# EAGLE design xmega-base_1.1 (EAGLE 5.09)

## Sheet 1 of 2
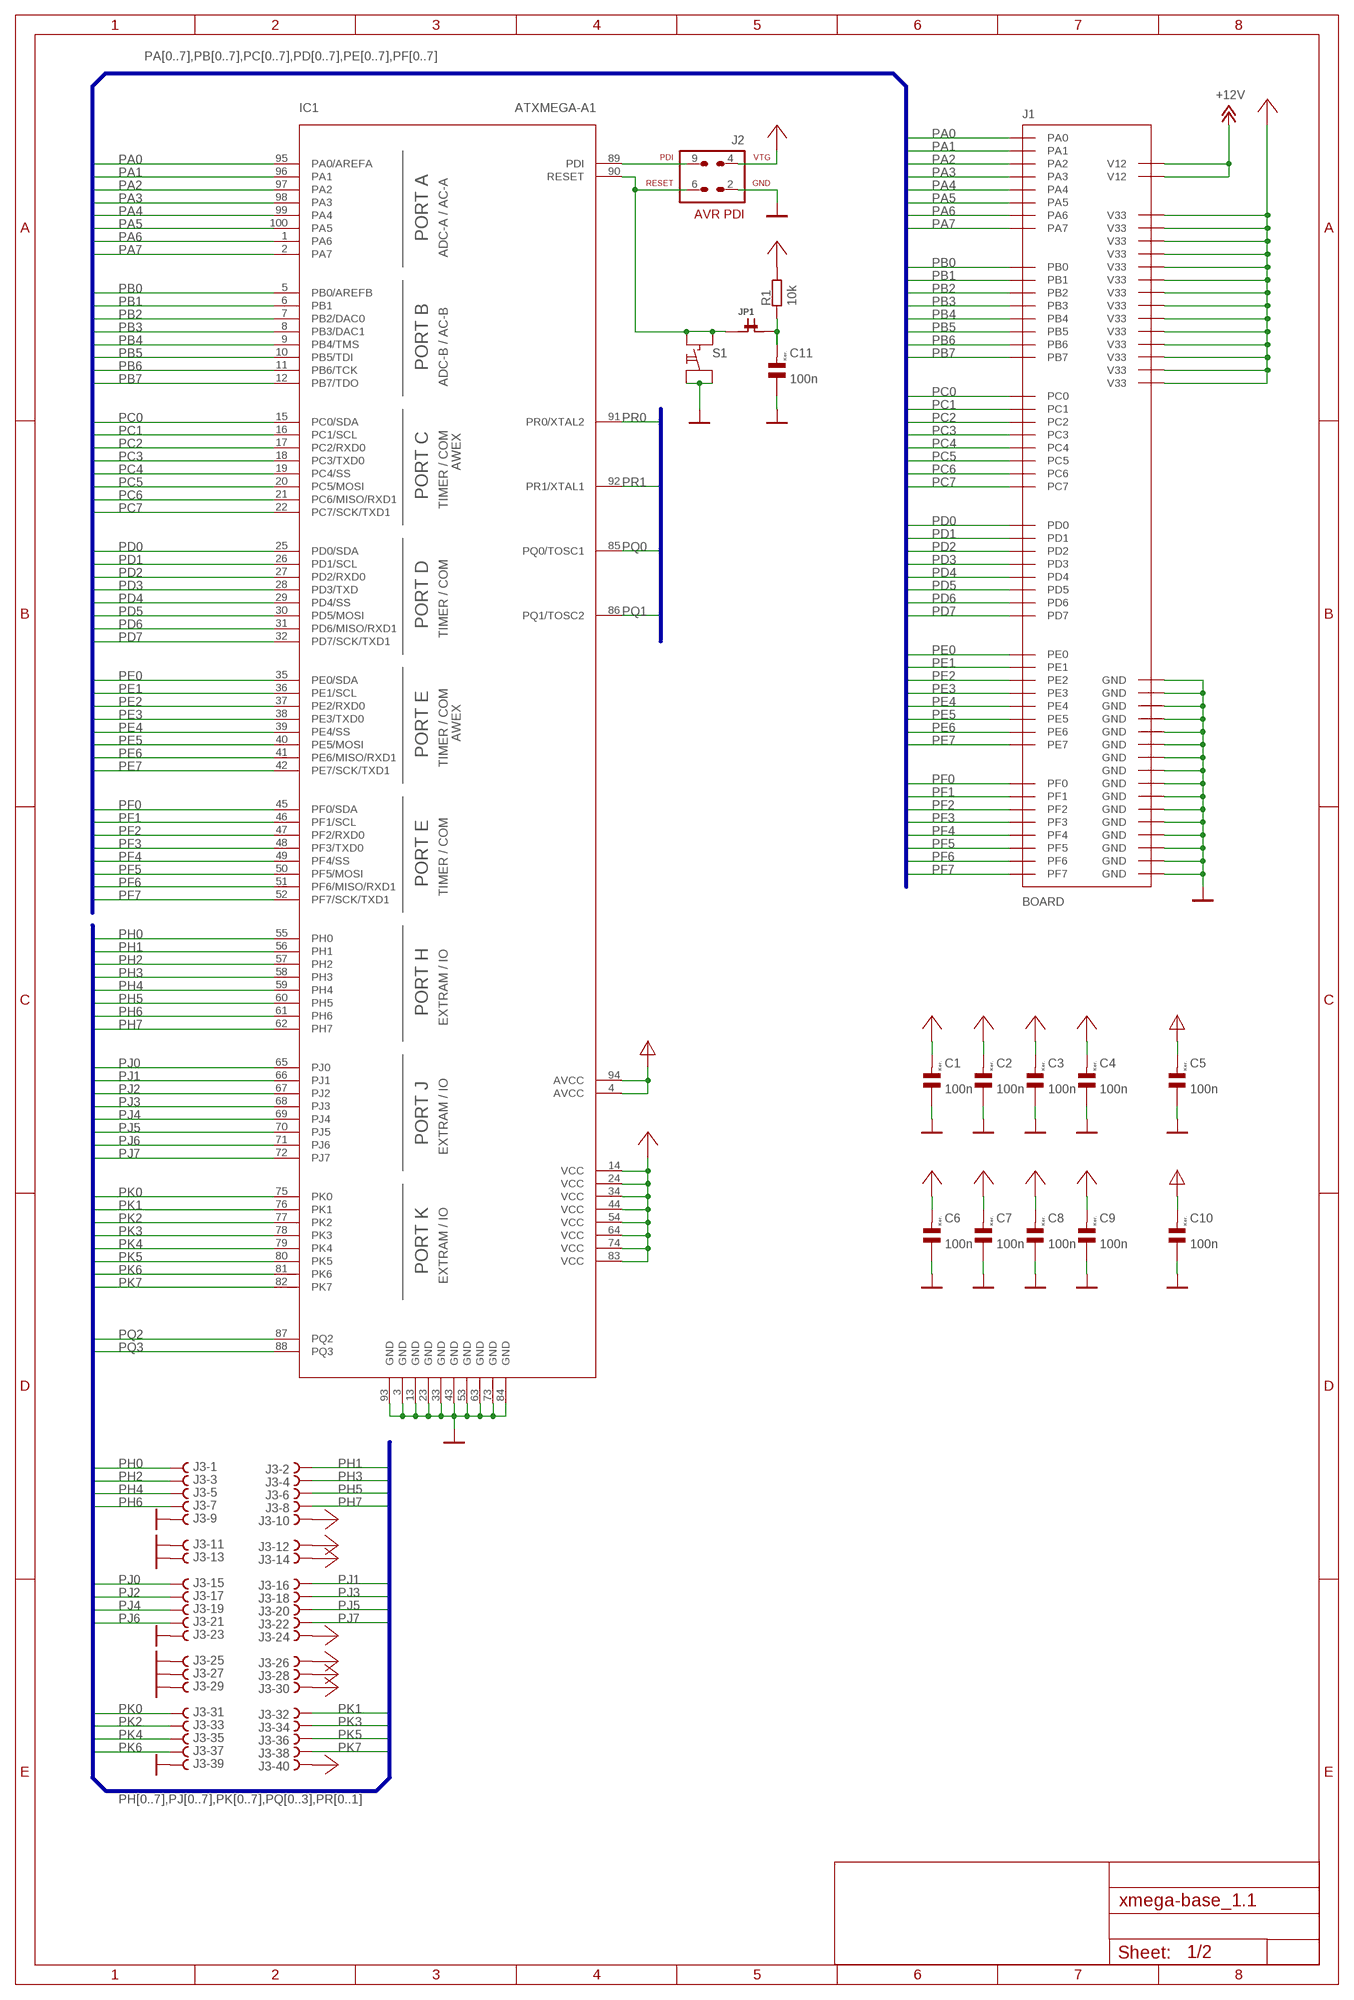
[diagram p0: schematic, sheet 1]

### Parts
C1  100n  C_KER_0805  [C0805K]
C2  100n  C_KER_0805  [C0805K]
C3  100n  C_KER_0805  [C0805K]
C4  100n  C_KER_0805  [C0805K]
C5  100n  C_KER_0805  [C0805K]
C6  100n  C_KER_0805  [C0805K]
C7  100n  C_KER_0805  [C0805K]
C8  100n  C_KER_0805  [C0805K]
C9  100n  C_KER_0805  [C0805K]
C10  100n  C_KER_0805  [C0805K]
C11  100n  C_KER_0805  [C0805K]
IC1  ATXMEGA-A1  [TQFP100]
J1  BOARD  [BOARD]
J2  AVR-PDIHW10  [ML10L]
J3  SL40S_2X20G_254  [SL2X20G_254]
JP1  JP1  [JP1]
R1  10k  R_0805  [R0805]
S1  PHAP3301  [PHAP3301]

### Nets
+12V: J1.P$1(V12) J1.P$2(V12) ; also sheet 2
AVCC: C5.2 C10.2 IC1.4(AVCC) IC1.94(AVCC) ; also sheet 2
GND: C1.1 C2.1 C3.1 C4.1 C5.1 C6.1 C7.1 C8.1 C9.1 C10.1 C11.1 IC1.3(GND) IC1.13(GND) IC1.23(GND) IC1.33(GND) IC1.43(GND) IC1.53(GND) IC1.63(GND) IC1.73(GND) IC1.84(GND) IC1.93(GND) J1.P$3(GND) J1.P$4(GND) J1.P$15(GND) J1.P$16(GND) J1.P$27(GND) J1.P$28(GND) J1.P$39(GND) J1.P$40(GND) J1.P$43(GND) J1.P$44(GND) J1.P$55(GND) J1.P$56(GND) J1.P$67(GND) J1.P$68(GND) J1.P$79(GND) J1.P$80(GND) J2.2(GND) J3.9 J3.11 J3.13 J3.23 J3.25 J3.27 J3.29 J3.39 S1.3 S1.4 ; also sheet 2
N$1: IC1.89(PDI) J2.9(PDI)
N$3: C11.2 JP1.2 R1.1
PA0: IC1.95(PA0/AREFA) J1.P$5(PA0)
PA1: IC1.96(PA1) J1.P$6(PA1)
PA2: IC1.97(PA2) J1.P$7(PA2)
PA3: IC1.98(PA3) J1.P$8(PA3)
PA4: IC1.99(PA4) J1.P$9(PA4)
PA5: IC1.100(PA5) J1.P$10(PA5)
PA6: IC1.1(PA6) J1.P$11(PA6)
PA7: IC1.2(PA7) J1.P$12(PA7)
PB0: IC1.5(PB0/AREFB) J1.P$17(PB0)
PB1: IC1.6(PB1) J1.P$18(PB1)
PB2: IC1.7(PB2/DAC0) J1.P$19(PB2)
PB3: IC1.8(PB3/DAC1) J1.P$20(PB3)
PB4: IC1.9(PB4/TMS) J1.P$21(PB4)
PB5: IC1.10(PB5/TDI) J1.P$22(PB5)
PB6: IC1.11(PB6/TCK) J1.P$23(PB6)
PB7: IC1.12(PB7/TDO) J1.P$24(PB7)
PC0: IC1.15(PC0/SDA) J1.P$29(PC0)
PC1: IC1.16(PC1/SCL) J1.P$30(PC1)
PC2: IC1.17(PC2/RXD0) J1.P$31(PC2)
PC3: IC1.18(PC3/TXD0) J1.P$32(PC3)
PC4: IC1.19(PC4/SS) J1.P$33(PC4)
PC5: IC1.20(PC5/MOSI) J1.P$34(PC5)
PC6: IC1.21(PC6/MISO/RXD1) J1.P$35(PC6)
PC7: IC1.22(PC7/SCK/TXD1) J1.P$36(PC7)
PD0: IC1.25(PD0/SDA) J1.P$76(PD0)
PD1: IC1.26(PD1/SCL) J1.P$75(PD1)
PD2: IC1.27(PD2/RXD0) J1.P$74(PD2) ; also sheet 2
PD3: IC1.28(PD3/TXD) J1.P$73(PD3) ; also sheet 2
PD4: IC1.29(PD4/SS) J1.P$72(PD4) ; also sheet 2
PD5: IC1.30(PD5/MOSI) J1.P$71(PD5) ; also sheet 2
PD6: IC1.31(PD6/MISO/RXD1) J1.P$70(PD6) ; also sheet 2
PD7: IC1.32(PD7/SCK/TXD1) J1.P$69(PD7) ; also sheet 2
PE0: IC1.35(PE0/SDA) J1.P$64(PE0)
PE1: IC1.36(PE1/SCL) J1.P$63(PE1)
PE2: IC1.37(PE2/RXD0) J1.P$62(PE2)
PE3: IC1.38(PE3/TXD0) J1.P$61(PE3)
PE4: IC1.39(PE4/SS) J1.P$60(PE4)
PE5: IC1.40(PE5/MOSI) J1.P$59(PE5)
PE6: IC1.41(PE6/MISO/RXD1) J1.P$58(PE6)
PE7: IC1.42(PE7/SCK/TXD1) J1.P$57(PE7)
PF0: IC1.45(PF0/SDA) J1.P$52(PF0)
PF1: IC1.46(PF1/SCL) J1.P$51(PF1)
PF2: IC1.47(PF2/RXD0) J1.P$50(PF2)
PF3: IC1.48(PF3/TXD0) J1.P$49(PF3)
PF4: IC1.49(PF4/SS) J1.P$48(PF4)
PF5: IC1.50(PF5/MOSI) J1.P$47(PF5)
PF6: IC1.51(PF6/MISO/RXD1) J1.P$46(PF6)
PF7: IC1.52(PF7/SCK/TXD1) J1.P$45(PF7)
PH0: IC1.55(PH0) J3.1
PH1: IC1.56(PH1) J3.2
PH2: IC1.57(PH2) J3.3
PH3: IC1.58(PH3) J3.4
PH4: IC1.59(PH4) J3.5
PH5: IC1.60(PH5) J3.6
PH6: IC1.61(PH6) J3.7
PH7: IC1.62(PH7) J3.8
PJ0: IC1.65(PJ0) J3.15
PJ1: IC1.66(PJ1) J3.16
PJ2: IC1.67(PJ2) J3.17
PJ3: IC1.68(PJ3) J3.18
PJ4: IC1.69(PJ4) J3.19
PJ5: IC1.70(PJ5) J3.20
PJ6: IC1.71(PJ6) J3.21
PJ7: IC1.72(PJ7) J3.22
PK0: IC1.75(PK0) J3.31
PK1: IC1.76(PK1) J3.32
PK2: IC1.77(PK2) J3.33
PK3: IC1.78(PK3) J3.34
PK4: IC1.79(PK4) J3.35
PK5: IC1.80(PK5) J3.36
PK6: IC1.81(PK6) J3.37
PK7: IC1.82(PK7) J3.38
PQ0: IC1.85(PQ0/TOSC1) ; also sheet 2
PQ1: IC1.86(PQ1/TOSC2) ; also sheet 2
PQ2: IC1.87(PQ2) ; also sheet 2
PQ3: IC1.88(PQ3) ; also sheet 2
PR0: IC1.91(PR0/XTAL2) ; also sheet 2
PR1: IC1.92(PR1/XTAL1) ; also sheet 2
RESET: IC1.90(RESET) J2.6(RESET) JP1.1 S1.1 S1.2
VCC: C1.2 C2.2 C3.2 C4.2 C6.2 C7.2 C8.2 C9.2 IC1.14(VCC) IC1.24(VCC) IC1.34(VCC) IC1.44(VCC) IC1.54(VCC) IC1.64(VCC) IC1.74(VCC) IC1.83(VCC) J1.P$13(V33) J1.P$14(V33) J1.P$25(V33) J1.P$26(V33) J1.P$37(V33) J1.P$38(V33) J1.P$41(V33) J1.P$42(V33) J1.P$53(V33) J1.P$54(V33) J1.P$65(V33) J1.P$66(V33) J1.P$77(V33) J1.P$78(V33) J2.4(VTG) J3.10 J3.12 J3.14 J3.24 J3.26 J3.28 J3.30 J3.40 R1.2 ; also sheet 2

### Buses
PA[0..7],PB[0..7],PC[0..7],PD[0..7],PE[0..7],PF[0..7]
PH[0..7],PJ[0..7],PK[0..7],PQ[0..3],PR[0..1]

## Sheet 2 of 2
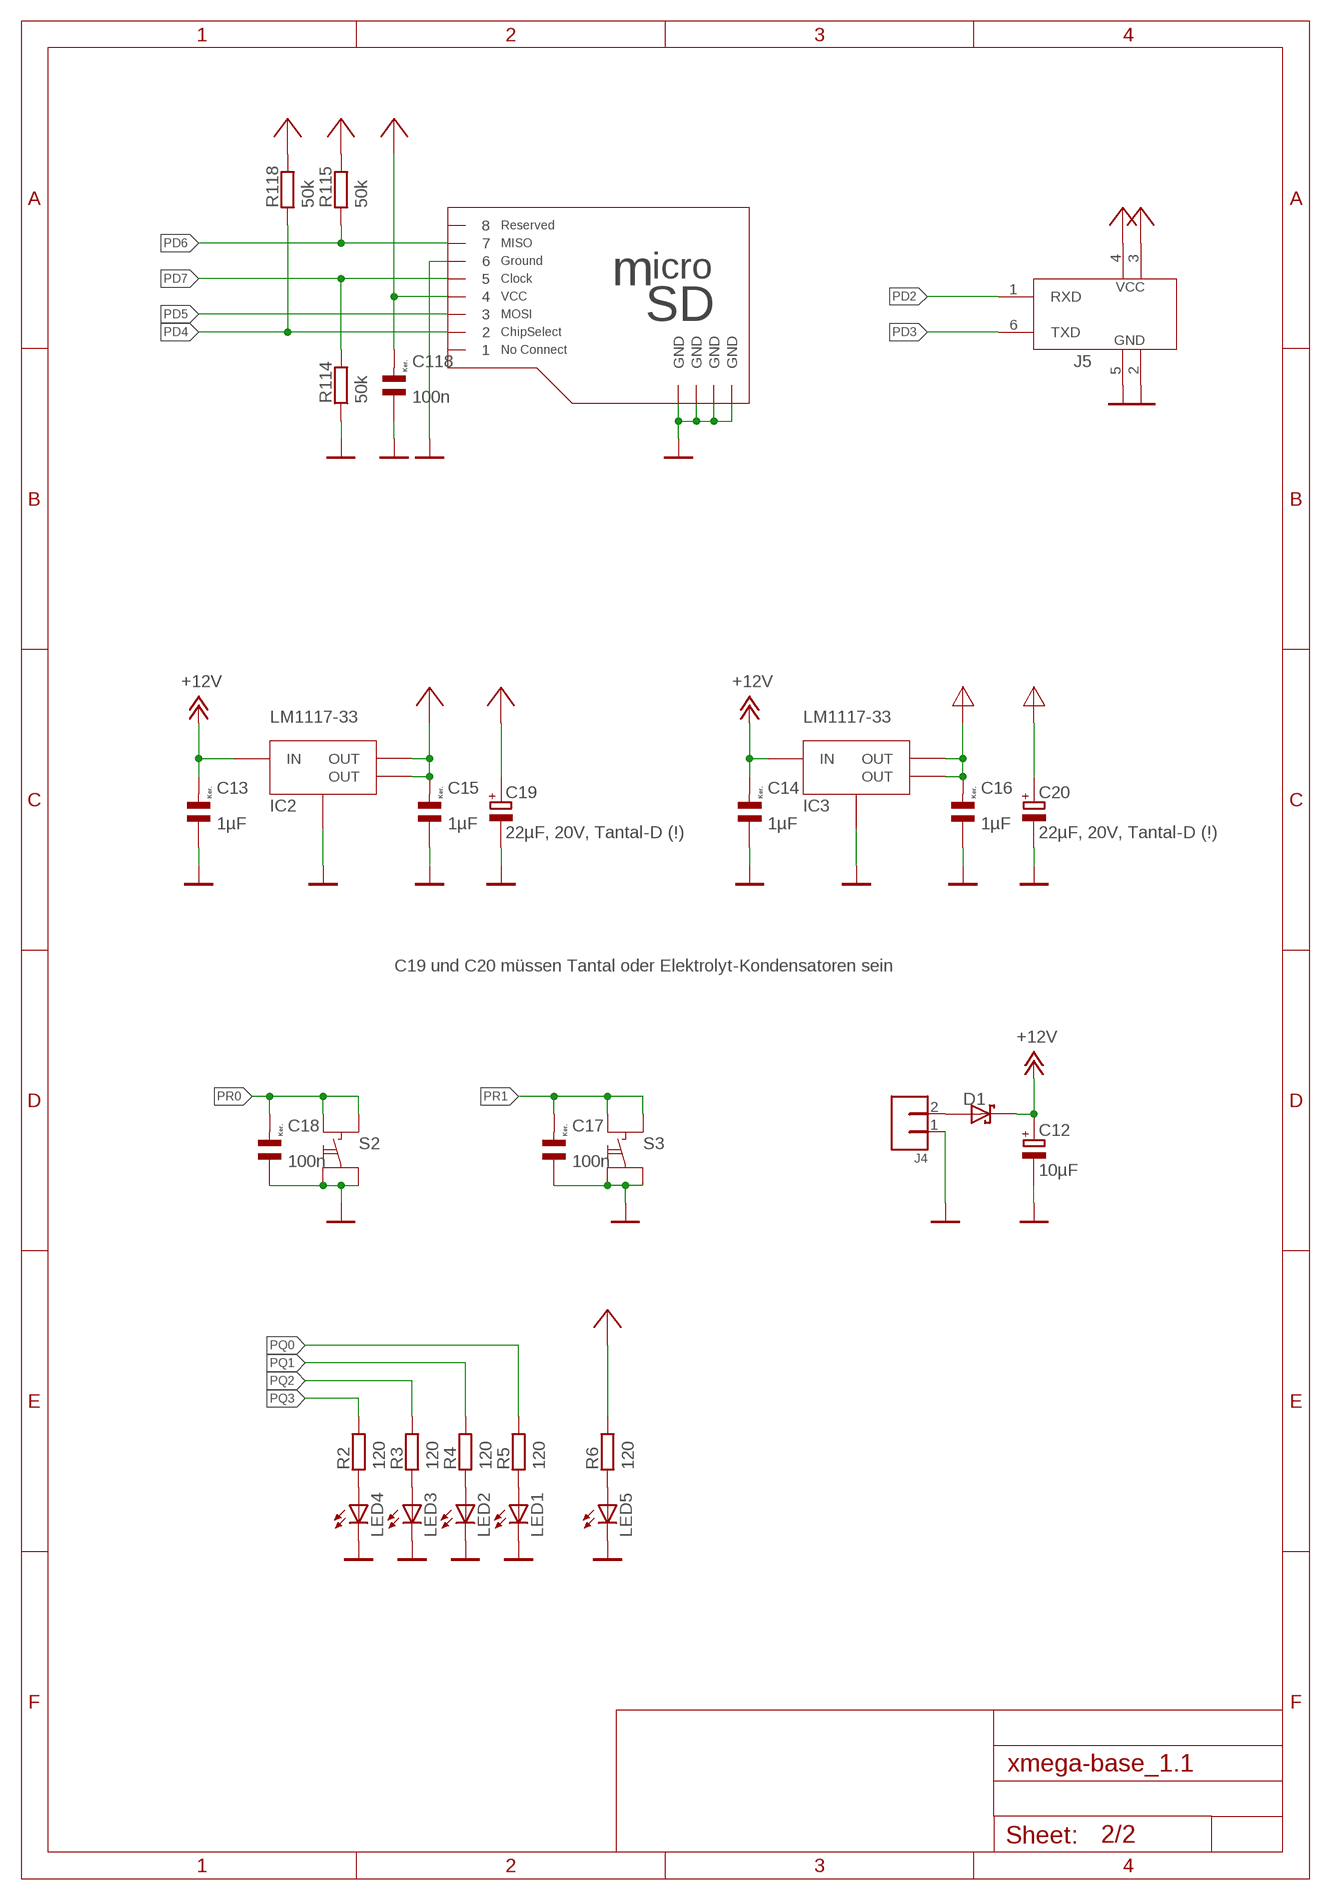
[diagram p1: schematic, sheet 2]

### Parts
C12  10µF  ELKO_SMD_05  [153CLV-0505]
C13  1µF  C_KER_1206  [C1206K]
C14  1µF  C_KER_1206  [C1206K]
C15  1µF  C_KER_1206  [C1206K]
C16  1µF  C_KER_1206  [C1206K]
C17  100n  C_KER_0805  [C0805K]
C18  100n  C_KER_0805  [C0805K]
C19  22µF, 20V, Tantal-D (!)  ELKO_SMD_D  [SMC_D]
C20  22µF, 20V, Tantal-D (!)  ELKO_SMD_D  [SMC_D]
C118  100n  C_KER_0805  [C0805K]
D1  SCHOTTKY-DIODE-SMB  [SMB]
IC2  LM1117-33  [SOT223]
IC3  LM1117-33  [SOT223]
J4  SL2_AKL_182  [AKL182-02]
J5  RS232_6PINHW  [ML6L]
J104  MICRO_SD_ST1  [JAE_ST1_MICOSD]
LED1  LEDCHIP-LED1206  [CHIPLED_1206]
LED2  LEDCHIP-LED1206  [CHIPLED_1206]
LED3  LEDCHIP-LED1206  [CHIPLED_1206]
LED4  LEDCHIP-LED1206  [CHIPLED_1206]
LED5  LEDCHIP-LED1206  [CHIPLED_1206]
R2  120  R_0805  [R0805]
R3  120  R_0805  [R0805]
R4  120  R_0805  [R0805]
R5  120  R_0805  [R0805]
R6  120  R_0805  [R0805]
R114  50k  R_0805  [R0805]
R115  50k  R_0805  [R0805]
R118  50k  R_0805  [R0805]
S2  PHAP3301  [PHAP3301]
S3  PHAP3301  [PHAP3301]

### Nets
+12V: C12.+ C13.2 C14.2 D1.C IC2.3(IN) IC3.3(IN) ; also sheet 1
AVCC: C16.2 C20.+ IC3.2(OUT) IC3.4(OUT) ; also sheet 1
GND: C12.- C13.1 C14.1 C15.1 C16.1 C17.1 C18.1 C19.- C20.- C118.1 IC2.1(GND) IC3.1(GND) J4.1 J5.2(GND) J5.5(GND) J104.6 J104.GND1(GND) J104.GND2(GND) J104.GND3(GND) J104.GND4(GND) LED1.C LED2.C LED3.C LED4.C LED5.C R114.1 S2.3 S2.4 S3.3 S3.4 ; also sheet 1
N$2: D1.A J4.2
N$4: LED4.A R2.1
N$5: LED3.A R3.1
N$6: LED2.A R4.1
N$7: LED1.A R5.1
N$8: LED5.A R6.1
PD2: J5.1(RXD) ; also sheet 1
PD3: J5.6(TXD) ; also sheet 1
PD4: J104.2 R118.1 ; also sheet 1
PD5: J104.3 ; also sheet 1
PD6: J104.7 R115.1 ; also sheet 1
PD7: J104.5 R114.2 ; also sheet 1
PQ0: R5.2 ; also sheet 1
PQ1: R4.2 ; also sheet 1
PQ2: R3.2 ; also sheet 1
PQ3: R2.2 ; also sheet 1
PR0: C18.2 S2.1 S2.2 ; also sheet 1
PR1: C17.2 S3.1 S3.2 ; also sheet 1
VCC: C15.2 C19.+ C118.2 IC2.2(OUT) IC2.4(OUT) J5.3(VCC) J5.4(VCC) J104.4 R6.2 R115.2 R118.2 ; also sheet 1
Unconnected: J104.1 J104.8

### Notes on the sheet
- C19 und C20 müssen Tantal oder Elektrolyt-Kondensatoren sein

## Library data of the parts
C1-C11 C13-C18 C118 = lib-rcl:C_KER
C12 C19 C20 = lib-rcl:ELKO
D1 = lib-halbleiter:SCHOTTKY-DIODE
IC1 = lib-avr:ATXMEGA-A1
IC2 IC3 = lib-ic:LM1117-*: Alternativ auch TLV1117 von TI
J1 = xmega-board:BOARD
J2 = lib-avr:AVR-PDI
J3 = lib-connectors:SL40S?
J4 = lib-connectors:SL2?
J5 = lib-com:RS232_6PIN
J104 = lib-misc:MICRO_SD
JP1 = lib-connectors:JP1
LED1-LED5 = lib-halbleiter:LED
R1-R6 R114 R115 R118 = lib-rcl:R: RESISTOR, European symbol
S1-S3 = lib-switch:PHAP?*

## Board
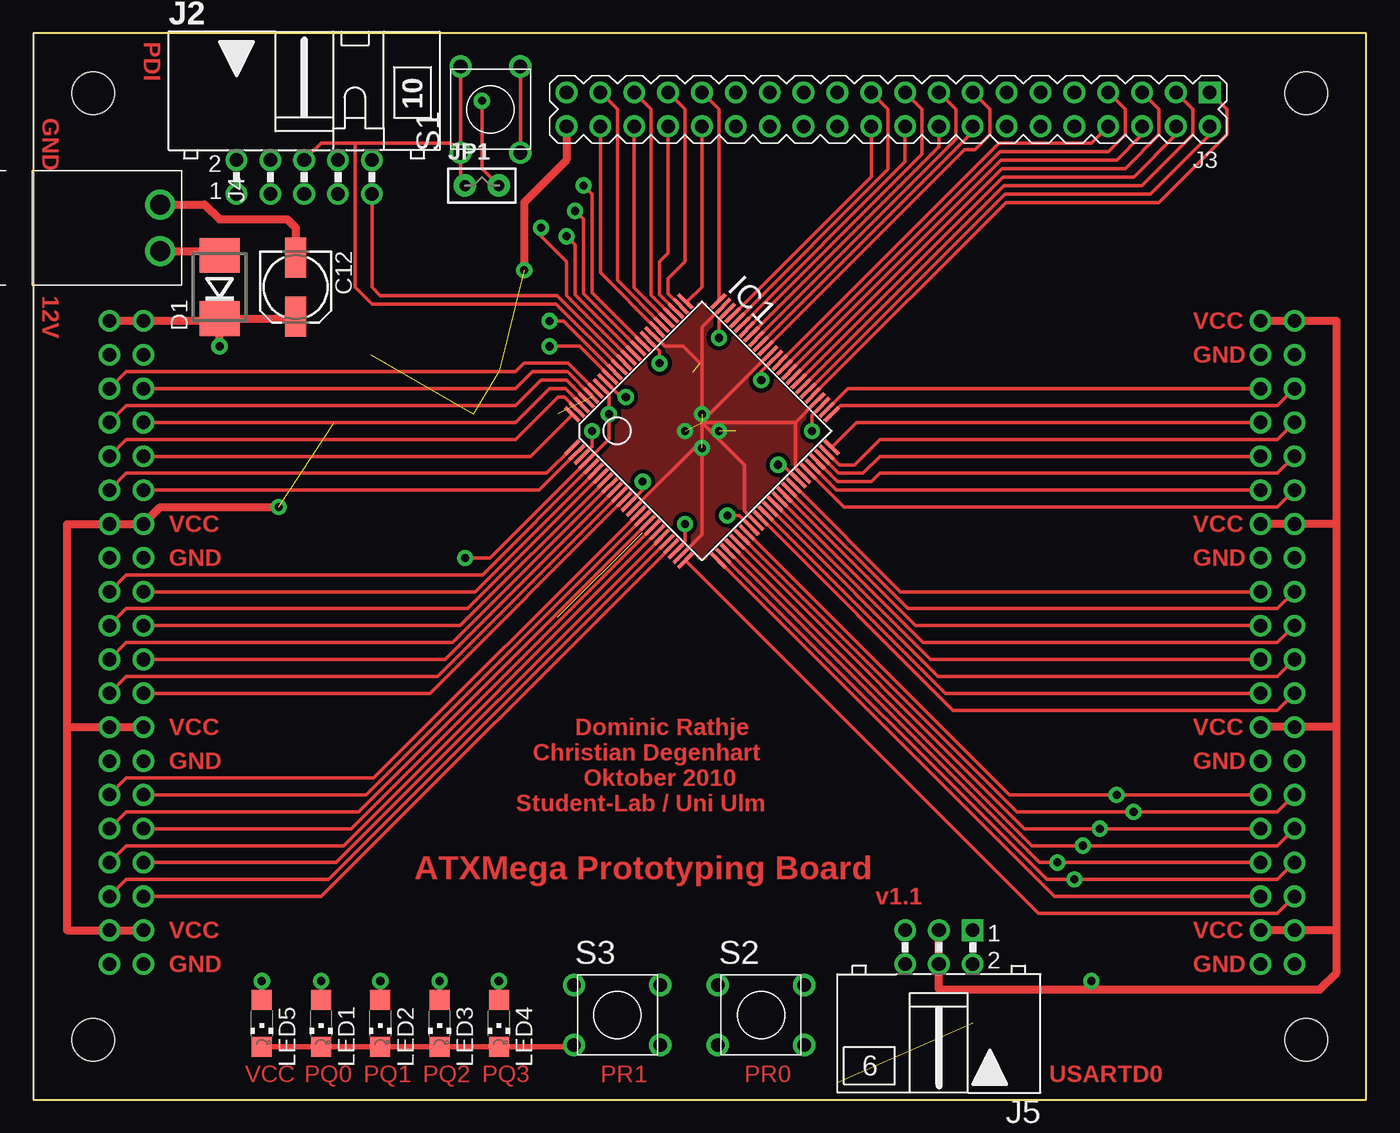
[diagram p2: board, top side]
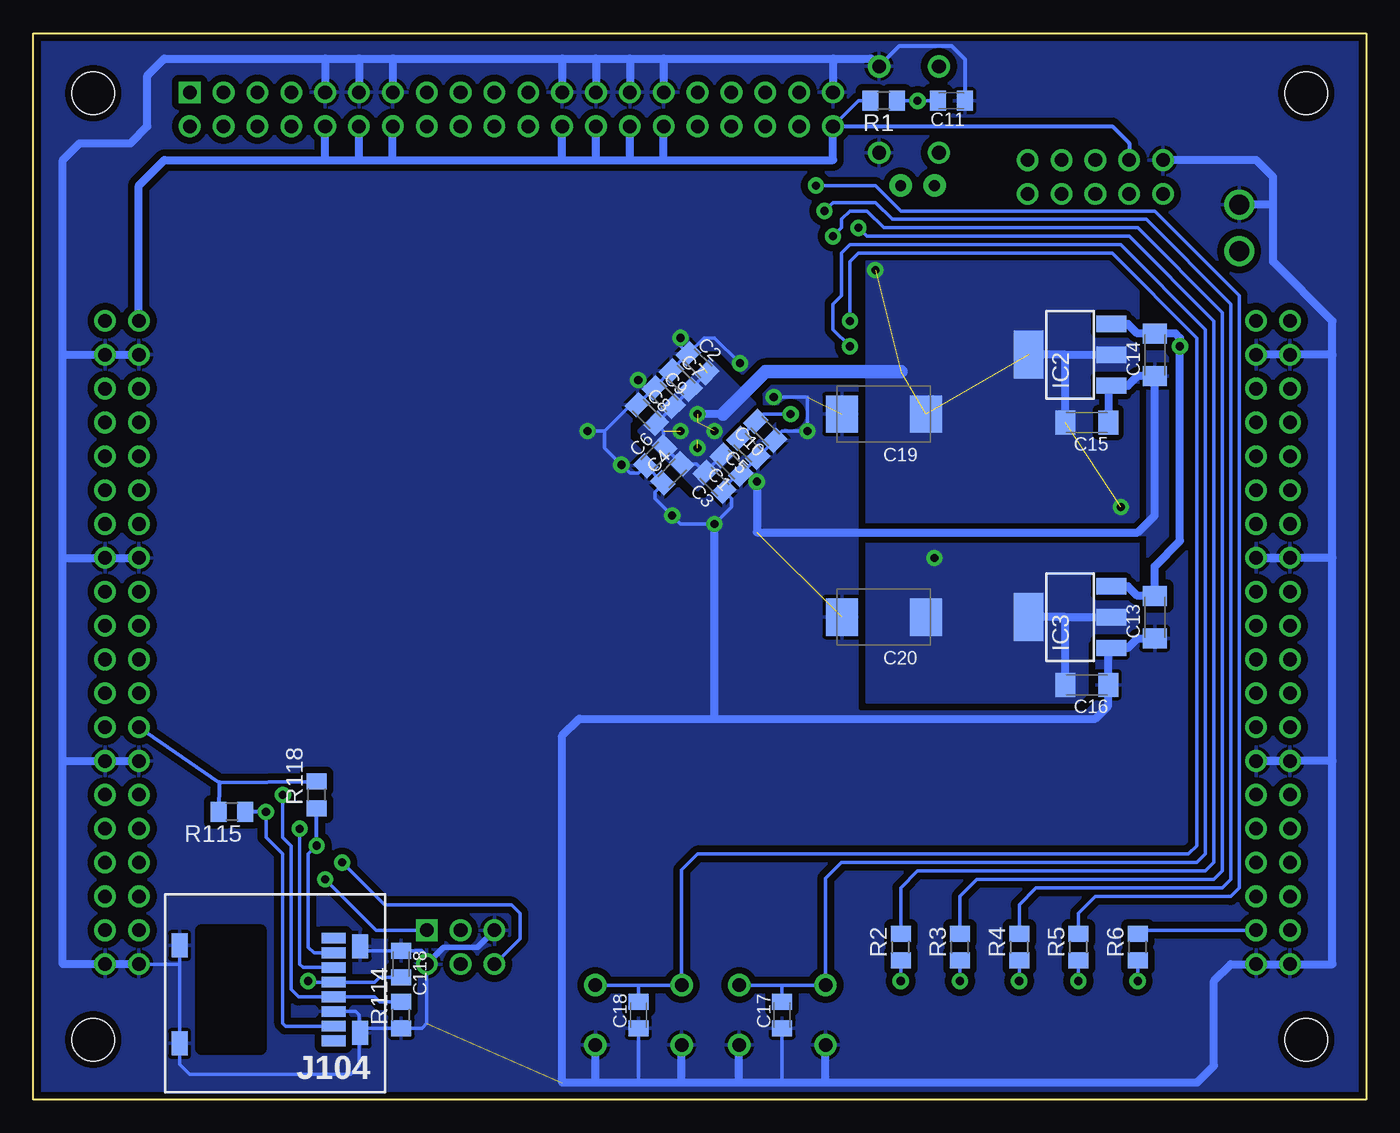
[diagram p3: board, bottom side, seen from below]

Size 100 x 80 mm. Coordinates in mm from the lower left corner, seen from the top.
Copper layers (1*16): Top 0.0254mm / dielectric 1.4986mm / Bottom 0.0254mm
Design rules "uni_ulm": minimum track width 8mil, minimum drill 16mil, track to track 8mil, track to pad 8mil, pad to pad 8mil, via to via 8mil, smd to smd 8mil, copper to edge 20mil, drill to drill 8mil, minimum pad ring 12mil, minimum via ring 12mil, stop-mask expansion 4mil, vias tented up to drill 24mil, thermal gap 10mil

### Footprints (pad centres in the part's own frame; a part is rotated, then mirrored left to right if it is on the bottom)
C0805K = smd 1.2 x 1.5: 1 -1,0; 2 1,0
153CLV-0505 = smd 3 x 1.6: + 2.2,0; - -2.2,0
C1206K = smd 1.5 x 1.8: 1 -1.6,0; 2 1.6,0
SMC_D = smd 2.4 x 2.8: + -3.15,0; - 3.15,0
SMB = smd 2.6 x 3: A 2.368,0; C -2.368,0
TQFP100 = smd 0.27 x 1.5: 1 -6,-7.75; 2 -5.5,-7.75; 3 -5,-7.75; 4 -4.5,-7.75; 5 -4,-7.75; 6 -3.5,-7.75; 7 -3,-7.75; 8 -2.5,-7.75; 9 -2,-7.75; 10 -1.5,-7.75; 11 -1,-7.75; 12 -0.5,-7.75; 13 0,-7.75; 14 0.5,-7.75; 15 1,-7.75; 16 1.5,-7.75; 17 2,-7.75; 18 2.5,-7.75; 19 3,-7.75; 20 3.5,-7.75; 21 4,-7.75; 22 4.5,-7.75; 23 5,-7.75; 24 5.5,-7.75; 25 6,-7.75; 51 6,7.75; 52 5.5,7.75; 53 5,7.75; 54 4.5,7.75; 55 4,7.75; 56 3.5,7.75; 57 3,7.75; 58 2.5,7.75; 59 2,7.75; 60 1.5,7.75; 61 1,7.75; 62 0.5,7.75; 63 0,7.75; 64 -0.5,7.75; 65 -1,7.75; 66 -1.5,7.75; 67 -2,7.75; 68 -2.5,7.75; 69 -3,7.75; 70 -3.5,7.75; 71 -4,7.75; 72 -4.5,7.75; 73 -5,7.75; 74 -5.5,7.75; 75 -6,7.75 | smd 1.5 x 0.27: 26 7.75,-6; 27 7.75,-5.5; 28 7.75,-5; 29 7.75,-4.5; 30 7.75,-4; 31 7.75,-3.5; 32 7.75,-3; 33 7.75,-2.5; 34 7.75,-2; 35 7.75,-1.5; 36 7.75,-1; 37 7.75,-0.5; 38 7.75,0; 39 7.75,0.5; 40 7.75,1; 41 7.75,1.5; 42 7.75,2; 43 7.75,2.5; 44 7.75,3; 45 7.75,3.5; 46 7.75,4; 47 7.75,4.5; 48 7.75,5; 49 7.75,5.5; 50 7.75,6; 76 -7.75,6; 77 -7.75,5.5; 78 -7.75,5; 79 -7.75,4.5; 80 -7.75,4; 81 -7.75,3.5; 82 -7.75,3; 83 -7.75,2.5; 84 -7.75,2; 85 -7.75,1.5; 86 -7.75,1; 87 -7.75,0.5; 88 -7.75,0; 89 -7.75,-0.5; 90 -7.75,-1; 91 -7.75,-1.5; 92 -7.75,-2; 93 -7.75,-2.5; 94 -7.75,-3; 95 -7.75,-3.5; 96 -7.75,-4; 97 -7.75,-4.5; 98 -7.75,-5; 99 -7.75,-5.5; 100 -7.75,-6
SOT223 = smd 1.219 x 2.235: 1 -2.311,-3.099; 2 0,-3.099; 3 2.311,-3.099 | smd 3.6 x 2.2: 4 0,3.099
BOARD = drill 1.016 pad 1.626 round: P$1 5.715,58.42; P$2 8.255,58.42; P$3 5.715,55.88; P$4 8.255,55.88; P$5 5.715,53.34; P$6 8.255,53.34; P$7 5.715,50.8; P$8 8.255,50.8; P$9 5.715,48.26; P$10 8.255,48.26; P$11 5.715,45.72; P$12 8.255,45.72; P$13 5.715,43.18; P$14 8.255,43.18; P$15 5.715,40.64; P$16 8.255,40.64; P$17 5.715,38.1; P$18 8.255,38.1; P$19 5.715,35.56; P$20 8.255,35.56; P$21 5.715,33.02; P$22 8.255,33.02; P$23 5.715,30.48; P$24 8.255,30.48; P$25 5.715,27.94; P$26 8.255,27.94; P$27 5.715,25.4; P$28 8.255,25.4; P$29 5.715,22.86; P$30 8.255,22.86; P$31 5.715,20.32; P$32 8.255,20.32; P$33 5.715,17.78; P$34 8.255,17.78; P$35 5.715,15.24; P$36 8.255,15.24; P$37 5.715,12.7; P$38 8.255,12.7; P$39 5.715,10.16; P$40 8.255,10.16; P$41 92.075,58.42; P$42 94.615,58.42; P$43 92.075,55.88; P$44 94.615,55.88; P$45 92.075,53.34; P$46 94.615,53.34; P$47 92.075,50.8; P$48 94.615,50.8; P$49 92.075,48.26; P$50 94.615,48.26; P$51 92.075,45.72; P$52 94.615,45.72; P$53 92.075,43.18; P$54 94.615,43.18; P$55 92.075,40.64; P$56 94.615,40.64; P$57 92.075,38.1; P$58 94.615,38.1; P$59 92.075,35.56; P$60 94.615,35.56; P$61 92.075,33.02; P$62 94.615,33.02; P$63 92.075,30.48; P$64 94.615,30.48; P$65 92.075,27.94; P$66 94.615,27.94; P$67 92.075,25.4; P$68 94.615,25.4; P$69 92.075,22.86; P$70 94.615,22.86; P$71 92.075,20.32; P$72 94.615,20.32; P$73 92.075,17.78; P$74 94.615,17.78; P$75 92.075,15.24; P$76 94.615,15.24; P$77 92.075,12.7; P$78 94.615,12.7; P$79 92.075,10.16; P$80 94.615,10.16 | hole 3.2: 4.5,4.5; 95.5,4.5; 95.5,75.5; 4.5,75.5
ML10L = drill 1.016 pad 1.626 round: 1 -5.08,-1.27; 2 -5.08,1.27; 3 -2.54,-1.27; 4 -2.54,1.27; 5 0,-1.27; 6 0,1.27; 7 2.54,-1.27; 8 2.54,1.27; 9 5.08,-1.27; 10 5.08,1.27
SL2X20G_254 = drill 1.016 pad 1.626 square: 1 -24.13,-1.27 | drill 1.016 pad 1.626 round: 2 -24.13,1.27; 3 -21.59,-1.27; 4 -21.59,1.27; 5 -19.05,-1.27; 6 -19.05,1.27; 7 -16.51,-1.27; 8 -16.51,1.27; 9 -13.97,-1.27; 10 -13.97,1.27; 11 -11.43,-1.27; 12 -11.43,1.27; 13 -8.89,-1.27; 14 -8.89,1.27; 15 -6.35,-1.27; 16 -6.35,1.27; 17 -3.81,-1.27; 18 -3.81,1.27; 19 -1.27,-1.27; 20 -1.27,1.27; 21 1.27,-1.27; 22 1.27,1.27; 23 3.81,-1.27; 24 3.81,1.27; 25 6.35,-1.27; 26 6.35,1.27; 27 8.89,-1.27; 28 8.89,1.27; 29 11.43,-1.27; 30 11.43,1.27; 31 13.97,-1.27; 32 13.97,1.27; 33 16.51,-1.27; 34 16.51,1.27; 35 19.05,-1.27; 36 19.05,1.27; 37 21.59,-1.27; 38 21.59,1.27; 39 24.13,-1.27; 40 24.13,1.27
AKL182-02 = drill 1.5 pad 2.184 round: 1 -1.75,0; 2 1.75,0
ML6L = drill 1.016 pad 1.626 square: 1 -2.54,-1.27 | drill 1.016 pad 1.626 round: 2 -2.54,1.27; 3 0,-1.27; 4 0,1.27; 5 2.54,-1.27; 6 2.54,1.27
JAE_ST1_MICOSD = smd 1.8 x 0.8: 1 0,-3.85; 2 0,-2.75; 3 0,-1.65; 4 0,-0.55; 5 0,0.55; 6 0,1.65; 7 0,2.75; 8 0,3.85 | smd 1.2 x 1.8: GND1 11.55,-3.3; GND2 11.55,4.05; GND3 -2,-3.25; GND4 -2,3.25
JP1 = drill 0.813 pad 1.676 round: 1 -1.27,0; 2 1.27,0
CHIPLED_1206 = smd 1.5 x 1.5: A 0,-1.75; C 0,1.75
R0805 = smd 1.2 x 1.5: 1 -1,0; 2 1,0
PHAP3301 = drill 1.016 pad 1.676 round: 1 -2.235,-3.251; 2 -2.235,3.226; 3 2.261,-3.251; 4 2.261,3.226

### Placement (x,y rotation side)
C1  47.62,47.62 135 bottom
C2  50.16,55.24 315 bottom
C3  48.9,46.35 135 bottom
C4  52.07,46.99 45 bottom
C5  46.35,48.9 135 bottom
C6  53.34,48.26 45 bottom
C7  51.44,53.98 315 bottom
C8  53.98,51.44 315 bottom
C9  52.7,52.7 315 bottom
C10  45.09,50.16 135 bottom
C11  31.11,74.93 180 bottom
C12  19.68,60.96 270 top
C13  15.88,36.2 90 bottom
C14  15.88,55.88 90 bottom
C15  20.95,50.8 180 bottom
C16  20.95,31.11 180 bottom
C17  43.81,6.35 90 bottom
C18  54.61,6.35 90 bottom
C19  36.2,51.44 180 bottom
C20  36.2,36.2 180 bottom
C118  72.39,10.16 270 bottom
D1  13.97,60.96 90 top
IC1  50.16,50.16 315 top
IC2  22.23,55.88 90 bottom
IC3  22.23,36.2 90 bottom
J1  0,0 0 top
J2  20.32,69.22 0 top
J3  64.14,74.3 180 top
J4  9.53,65.41 270 top
J5  67.94,11.43 180 top
J104  77.47,8.26 180 bottom
JP1  33.66,68.58 0 top
LED1  21.59,5.71 180 top
LED2  26.04,5.71 180 top
LED3  30.48,5.71 180 top
LED4  34.92,5.71 180 top
LED5  17.14,5.71 180 top
R1  36.2,74.93 180 bottom
R2  34.92,11.43 90 bottom
R3  30.48,11.43 90 bottom
R4  26.04,11.43 90 bottom
R5  21.59,11.43 90 bottom
R6  17.14,11.43 90 bottom
R114  72.39,6.35 90 bottom
R115  85.09,21.59 180 bottom
R118  78.74,22.86 90 bottom
S1  34.29,74.3 0 top
S2  54.61,6.35 270 top
S3  43.81,6.35 270 top

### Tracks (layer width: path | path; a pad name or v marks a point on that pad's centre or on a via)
+12V  (via drill 0.61 pad 0.81)
  Top 0.305: 13.97,58.42 D1.C
  Top 0.61: J1.P$1 J1.P$2 13.97,58.42 v13.97,56.52 | C12.+ 19.52,58.59 D1.C
  Bottom 0.61: IC3.3 17.87,38.51 17.16,37.8 C13.2 15.88,40.01 13.97,41.91 v13.97,56.52 13.97,57.15 14.3,57.48 C14.2 17.16,57.48 17.87,58.19 IC2.3
AVCC  (via drill 0.61 pad 0.81)
  Top 0.254: IC1.94 43.18,52.91 v43.18,51.44 43.18,49.53 43.17,49.53 IC1.4 34.28,40.64 v32.38,40.64
  Bottom 0.254: C5.2 C10.2 45.23,51.44 v43.18,51.44
  Bottom 0.61: 22.55,36.2 IC3.2 | C16.2 22.55,36.2 | 22.55,36.2 IC3.4
  pour Bottom (isolate 0.406, no thermals): 17.14,41.91 17.14,34.92 20.32,34.92 20.95,34.29 20.95,30.48 21.59,29.84 37.47,29.84 37.47,41.91
GND  (via drill 0.61 pad 0.81)  (3 unrouted)
  Top 0.254: IC1.53 58.42,51.35 v58.42,50.16 | IC1.73 51.44,58.51 v51.44,57.15 | IC1.63 54.61,54.61 v54.61,53.98 | IC1.3 41.91,48.98 v41.91,50.16 | IC1.23 48.9,41.82 v48.9,43.18 | IC1.13 45.72,45.72 v45.72,46.35 | IC1.33 52.98,43.81 v52.07,43.81 | IC1.43 56.24,47.62 v55.88,47.62 | IC1.93 44.09,52.7 v44.45,52.7 | IC1.84 46.99,56.17 v46.99,55.24 | S1.4 S1.3
  Top 0.406: LED5.C LED1.C LED2.C LED3.C LED4.C 40.44,3.96 S3.3
  Top 0.61: 19.68,63.5 C12.- 19.68,65.41 19.05,66.04 13.97,66.04 12.86,67.16 J4.1
  Bottom 0.254: C1.1 47.06,47.06 48.19,45.94 C3.1 47.62,45.09 47.62,44.45 v48.9,43.18 51.44,43.18 v52.07,43.81 53.34,45.09 53.34,45.58 52.7,46.21 C4.1 C6.1 54.61,46.99 55.24,46.99 v55.88,47.62 | C9.1 C8.1 54.75,52.07 55.24,52.07 57.15,50.16 | C9.1 C7.1 | C7.1 52,54.54 | C2.1 50.87,55.66 | C7.1 C2.1 | v51.44,57.15 51.44,56.52 C2.1 | C2.1 | 57.15,50.16 v58.42,50.16 | C9.1 | C1.1 C5.1 C10.1 44.38,49.6 43.81,50.16 v41.91,50.16 41.91,52.7 v44.45,52.7 | v45.72,46.35 46.28,46.92 C1.1 | v54.61,53.98 54.05,53.41 C9.1 | 57.15,50.16 57.15,48.9 v55.88,47.62 | v55.88,47.62 55.81,47.55 | v46.99,55.24 48.9,57.15 49.67,57.15 C2.1 | 75.12,5.35 R114.1 70.85,5.35 70.48,5.71 J5.2 70.48,10.79 70.85,11.16 C118.1 75.12,11.16 J104.GND3 | 75.12,5.35 J104.GND4 75.56,4.91 75.56,2.54 76.2,1.91 88.27,1.91 89.02,2.66 J104.GND2 89.02,10.16 | J104.6 75.82,6.61 75.56,6.35 75.56,5.79 75.12,5.35 | 89.02,10.16 J104.GND1 | 89.02,10.16 J1.P$79 | 43.81,1.27 C17.1 | 54.61,1.27 C18.1
  Bottom 0.305: C11.1 30.11,78.06 31.11,79.06 35.01,79.06 S1.4
  Bottom 0.406: J5.5 66.67,11.43 69.22,11.43 J5.2
  Bottom 0.61: J1.P$79 J1.P$80 97.79,10.16 97.79,25.4 | J1.P$55 J1.P$56 97.79,40.64 | J1.P$43 J1.P$44 97.79,55.88 | J1.P$40 J1.P$39 | J1.P$27 J1.P$28 2.54,25.4 | J1.P$15 J1.P$16 2.54,40.64 | J1.P$4 J1.P$3 2.54,55.88 | J2.2 8.26,70.48 6.99,69.22 6.99,67.31 | 6.99,67.31 6.99,62.87 2.54,58.42 2.54,55.88 | J4.1 7.14,67.16 6.99,67.31 | C13.1 17.16,34.59 17.87,33.88 IC3.1 19.36,33.66 C16.1 19.36,29.54 20.32,28.57 48.9,28.57 | C15.1 19.36,53.34 IC2.1 17.87,53.57 17.16,54.28 C14.1 15.88,43.81 17.14,42.55 45.72,42.55 v45.72,46.35 | J1.P$40 2.54,10.16 2.54,25.4 | 2.54,25.4 2.54,40.64 | 2.54,40.64 2.54,55.88 | 97.79,25.4 97.79,40.64 | 97.79,40.64 97.79,55.88 | 97.79,25.4 J1.P$68 J1.P$67 | 40.01,78.11 J3.39 | 52.7,78.11 40.01,78.11 | 55.24,78.11 52.7,78.11 | 57.78,78.11 55.24,78.11 | 60.33,78.11 57.78,78.11 | 73.03,78.11 60.33,78.11 | 75.56,78.11 73.03,78.11 | 78.11,78.11 75.56,78.11 | 75.56,78.11 J3.11 | 73.03,78.11 J3.13 | 60.33,78.11 J3.23 | 57.78,78.11 J3.25 | 55.24,78.11 J3.27 | 52.7,78.11 J3.29 | 78.11,78.11 J3.9 | 78.11,78.11 90.17,78.11 91.44,76.83 91.44,73.03 92.71,71.75 96.52,71.75 97.79,70.48 97.79,55.88 | 40.01,78.11 37.13,78.11 S1.4 | 48.9,28.57 v48.9,43.18 | J1.P$40 10.16,10.16 11.43,8.89 11.43,2.54 12.7,1.27 40.64,1.27 | 48.9,28.57 59.05,28.57 60.33,27.3 60.33,1.27 57.78,1.27 | 40.64,1.27 43.81,1.27 46.99,1.27 | 46.99,1.27 51.44,1.27 | 51.44,1.27 54.61,1.27 57.78,1.27 | S2.4 57.84,1.32 57.78,1.27 | S2.3 51.36,1.35 51.44,1.27 | S3.4 47.04,1.32 46.99,1.27 | S3.3 40.56,1.35 40.64,1.27
  pour Bottom (isolate 0.508, rank 3): -0.64,80.64 -0.64,0 100.33,0 100.33,80.64
N$1
  Top 0.254: IC1.89 39.3,60.33 26.04,60.33 25.4,60.96 J2.9
N$2
  Top 0.61: J4.2 13.97,63.66 D1.A
N$3  (via drill 0.61 pad 0.81)
  Top 0.254: v33.66,74.93 33.66,69.85 JP1.2
  Bottom 0.254: R1.1 v33.66,74.93 C11.2
N$4  (via drill 0.61 pad 0.81)
  Top 0.254: LED4.A v34.92,8.89
  Bottom 0.254: v34.92,8.89 R2.1
N$5  (via drill 0.61 pad 0.81)
  Top 0.254: LED3.A v30.48,8.89
  Bottom 0.254: v30.48,8.89 R3.1
N$6  (via drill 0.61 pad 0.81)
  Top 0.254: LED2.A v26.04,8.89
  Bottom 0.254: v26.04,8.89 R4.1
N$7  (via drill 0.61 pad 0.81)
  Top 0.254: LED1.A v21.59,8.89
  Bottom 0.254: v21.59,8.89 R5.1
N$8  (via drill 0.61 pad 0.81)
  Top 0.254: LED5.A v17.14,8.89
  Bottom 0.254: v17.14,8.89 R6.1
PA0
  Top 0.254: J1.P$5 6.99,54.61 36.2,54.61 36.83,55.24 40.13,55.24 IC1.95
PA1
  Top 0.254: IC1.96 40.06,54.61 37.47,54.61 36.2,53.34 J1.P$6
PA2
  Top 0.254: IC1.97 39.99,53.98 38.1,53.98 36.2,52.07 6.99,52.07 J1.P$7
PA3
  Top 0.254: IC1.98 39.92,53.34 38.73,53.34 36.2,50.8 J1.P$8
PA4
  Top 0.254: IC1.99 39.85,52.7 39.37,52.7 36.2,49.53 6.99,49.53 J1.P$9
PA5
  Top 0.254: IC1.100 37.3,48.26 J1.P$10
PA6
  Top 0.254: IC1.1 38.51,46.99 6.99,46.99 J1.P$11
PA7
  Top 0.254: IC1.2 37.94,45.72 J1.P$12
PB0
  Top 0.254: IC1.5 33.71,39.37 6.99,39.37 J1.P$17
PB1
  Top 0.254: IC1.6 33.15,38.1 J1.P$18
PB2
  Top 0.254: IC1.7 32.59,36.83 6.99,36.83 J1.P$19
PB3
  Top 0.254: IC1.8 32.02,35.56 J1.P$20
PB4
  Top 0.254: IC1.9 31.46,34.29 6.99,34.29 J1.P$21
PB5
  Top 0.254: IC1.10 30.9,33.02 J1.P$22
PB6
  Top 0.254: IC1.11 30.34,31.75 6.99,31.75 J1.P$23
PB7
  Top 0.254: IC1.12 29.77,30.48 J1.P$24
PC0
  Top 0.254: IC1.15 25.54,24.13 6.99,24.13 J1.P$29
PC1
  Top 0.254: IC1.16 24.98,22.86 J1.P$30
PC2
  Top 0.254: IC1.17 24.42,21.59 6.99,21.59 J1.P$31
PC3
  Top 0.254: IC1.18 23.86,20.32 J1.P$32
PC4
  Top 0.254: IC1.19 23.29,19.05 6.99,19.05 J1.P$33
PC5
  Top 0.254: IC1.20 22.73,17.78 J1.P$34
PC6
  Top 0.254: IC1.21 22.17,16.51 6.99,16.51 J1.P$35
PC7
  Top 0.254: IC1.22 21.6,15.24 J1.P$36
PD0
  Top 0.254: IC1.25 75.4,13.97 93.34,13.97 J1.P$76
PD1
  Top 0.254: IC1.26 76.61,15.24 J1.P$75
PD2  (via drill 0.61 pad 0.81)
  Top 0.254: IC1.27 76.04,16.51 v78.11,16.51 93.34,16.51 J1.P$74
  Bottom 0.254: J5.1 74.3,12.7 v78.11,16.51
PD3  (via drill 0.61 pad 0.81)
  Top 0.254: IC1.28 75.48,17.78 v76.83,17.78 J1.P$73
  Bottom 0.254: J5.6 63.5,12.06 63.5,13.97 64.14,14.61 73.66,14.61 v76.83,17.78
PD4  (via drill 0.61 pad 0.81)
  Top 0.254: IC1.29 74.92,19.05 v78.74,19.05 93.34,19.05 J1.P$72
  Bottom 0.254: J104.2 78.95,11.01 79.38,11.43 79.38,18.41 v78.74,19.05
  Bottom 0.305: v78.74,19.05 R118.1
PD5  (via drill 0.61 pad 0.81)
  Top 0.254: IC1.30 74.35,20.32 v80.01,20.32 J1.P$71
  Bottom 0.254: J104.3 79.75,9.9 80.01,10.16 v80.01,20.32
PD6  (via drill 0.61 pad 0.81)
  Top 0.254: IC1.31 73.79,21.59 v82.55,21.59 93.34,21.59 J1.P$70
  Bottom 0.254: J104.7 81.07,5.5 81.28,5.71 81.28,18.41 82.55,19.68 v82.55,21.59
  Bottom 0.305: v82.55,21.59 R115.1
PD7  (via drill 0.61 pad 0.81)
  Top 0.254: J1.P$69 v81.28,22.86 73.23,22.86 IC1.32
  Bottom 0.254: v81.28,22.86 81.28,19.68 80.64,19.05 80.64,8.26 80.09,7.71 J104.5 74.38,7.71 74.03,7.35 R114.2
PE0
  Top 0.254: IC1.35 69,29.21 93.34,29.21 J1.P$64
PE1
  Top 0.254: IC1.36 68.44,30.48 J1.P$63
PE2
  Top 0.254: IC1.37 67.87,31.75 93.34,31.75 J1.P$62
PE3
  Top 0.254: IC1.38 67.31,33.02 J1.P$61
PE4
  Top 0.254: IC1.39 66.75,34.29 93.34,34.29 J1.P$60
PE5
  Top 0.254: IC1.40 66.18,35.56 J1.P$59
PE6
  Top 0.254: IC1.41 65.62,36.83 93.34,36.83 J1.P$58
PE7
  Top 0.254: IC1.42 65.06,38.1 J1.P$57
PF0
  Top 0.254: IC1.45 60.83,44.45 93.34,44.45 J1.P$52
PF1
  Top 0.254: IC1.46 60.27,45.72 J1.P$51
PF2
  Top 0.254: IC1.47 60.34,46.35 62.87,46.35 63.5,46.99 93.34,46.99 J1.P$50
PF3
  Top 0.254: IC1.48 60.41,46.99 62.23,46.99 63.5,48.26 J1.P$49
PF4
  Top 0.254: IC1.49 60.48,47.62 61.59,47.62 63.5,49.53 93.34,49.53 J1.P$48
PF5
  Top 0.254: IC1.50 61.76,50.8 J1.P$47
PF6
  Top 0.254: IC1.51 60.55,52.07 93.34,52.07 J1.P$46
PF7
  Top 0.254: IC1.52 61.12,53.34 J1.P$45
PH0
  Top 0.254: J3.1 89.53,74.3 89.53,72.39 84.45,67.31 72.97,67.31 IC1.55
PH1
  Top 0.254: J3.2 88.27,72.39 83.82,67.94 72.89,67.94 IC1.56
PH2
  Top 0.254: J3.3 87,74.3 87,72.39 83.19,68.58 72.82,68.58 IC1.57
PH3
  Top 0.254: J3.4 85.72,72.39 82.55,69.22 72.75,69.22 IC1.58
PH4
  Top 0.254: J3.5 84.45,74.3 84.45,72.39 81.92,69.85 72.68,69.85 IC1.59
PH5
  Top 0.254: J3.6 83.19,72.39 81.28,70.48 72.61,70.48 IC1.60
PH6
  Top 0.254: J3.7 81.92,74.3 81.92,72.39 80.64,71.12 72.53,71.12 IC1.61
PH7
  Top 0.254: J3.8 79.38,71.75 72.46,71.75 IC1.62
PJ0
  Top 0.254: IC1.65 69.85,71.26 70.63,71.26 71.75,72.39 71.75,74.3 J3.15
PJ1
  Top 0.254: IC1.66 70.48,72.61 J3.16
PJ2
  Top 0.254: J3.17 69.22,74.3 69.22,72.04 IC1.67
PJ3
  Top 0.254: IC1.68 67.94,71.48 J3.18
PJ4
  Top 0.254: J3.19 66.67,74.3 66.67,70.92 IC1.69
PJ5
  Top 0.254: IC1.70 65.41,70.36 J3.20
PJ6
  Top 0.254: J3.21 64.14,74.3 64.14,69.79 IC1.71
PJ7
  Top 0.254: IC1.72 62.87,69.23 J3.22
PK0
  Top 0.254: J3.31 51.44,74.3 51.44,59.92 IC1.75
PK1
  Top 0.254: IC1.76 49.09,59.89 50.16,60.96 J3.32
PK2
  Top 0.254: J3.33 48.9,74.3 48.9,62.87 47.62,61.59 47.62,60.48 IC1.77
PK3
  Top 0.254: IC1.78 46.99,60.41 46.99,62.87 47.62,63.5 47.62,64.77 J3.34
PK4
  Top 0.254: J3.35 46.35,74.3 46.35,60.34 IC1.79
PK5
  Top 0.254: IC1.80 45.09,60.9 J3.36
PK6
  Top 0.254: J3.37 43.81,74.3 43.81,61.47 IC1.81
PK7
  Top 0.254: IC1.82 42.55,62.03 J3.38
PQ0  (via drill 0.61 pad 0.81)
  Top 0.254: IC1.85 41.91,60.54 41.91,67.94 v41.27,68.58
  Bottom 0.254: v41.27,68.58 36.83,68.58 34.92,66.67 15.88,66.67 9.53,60.33 9.53,15.88 10.16,15.24 20.32,15.24 21.59,13.97 R5.2
PQ1  (via drill 0.61 pad 0.81)
  Top 0.254: IC1.86 41.27,60.47 41.27,66.04 v40.64,66.67
  Bottom 0.254: v40.64,66.67 40.01,67.31 36.83,67.31 35.56,66.04 16.51,66.04 10.16,59.69 10.16,16.51 10.79,15.88 24.77,15.88 26.04,14.61 R4.2
PQ2  (via drill 0.61 pad 0.81)
  Top 0.254: IC1.87 40.64,60.4 40.64,64.14 v40.01,64.77
  Bottom 0.254: v40.01,64.77 39.37,65.41 39.37,66.04 38.73,66.67 37.47,66.67 36.2,65.41 17.14,65.41 10.79,59.05 10.79,17.14 11.43,16.51 29.21,16.51 30.48,15.24 R3.2
PQ3  (via drill 0.61 pad 0.81)
  Top 0.254: IC1.88 40.01,60.33 40.01,62.87 38.1,64.77 v38.1,65.41
  Bottom 0.254: v38.1,65.41 37.47,64.77 17.78,64.77 11.43,58.42 11.43,17.78 12.06,17.14 33.66,17.14 34.92,15.88 R2.2
PR0  (via drill 0.61 pad 0.81)
  Top 0.254: IC1.91 39.79,58.42 v38.73,58.42
  Bottom 0.254: v38.73,58.42 38.73,62.87 38.1,63.5 19.05,63.5 12.7,57.15 12.7,19.05 13.34,18.41 50.16,18.41 51.36,17.22 S2.1 54.61,8.59 | 54.61,8.59 S2.2 | 54.61,8.59 C18.2
PR1  (via drill 0.61 pad 0.81)
  Top 0.254: IC1.92 40.99,56.52 v38.73,56.52
  Bottom 0.254: v38.73,56.52 40.01,57.78 40.01,59.69 39.37,60.33 39.37,63.5 38.73,64.14 18.41,64.14 12.06,57.78 12.06,18.41 12.7,17.78 39.37,17.78 40.56,16.59 S3.1 43.81,8.59 | 43.81,8.59 S3.2 | 43.81,8.59 C17.2
RESET
  Top 0.254: S1.1 S1.2 | S1.1 32.05,68.91 JP1.1 | J2.6 21.59,71.75 24.13,71.75 | 24.13,71.75 31.34,71.75 S1.1 | IC1.90 39.23,59.69 25.4,59.69 24.13,60.96 24.13,71.75
VCC  (via drill 0.61 pad 0.81)  (9 unrouted)
  Top 0.254: IC1.14 50.16,49.46 | 50.16,50.87 IC1.64 | 50.16,49.46 50.16,50.8 | 50.16,50.8 50.16,50.87 | 57.15,47.42 IC1.44 57.16,47.41 57.16,50.8 | 57.16,50.8 IC1.54 | IC1.83 47.35,56.52 48.74,56.52 50.01,55.24 50.16,55.24 | IC1.24 50.16,42.39 50.16,49.46 | IC1.74 50.16,57.94 50.16,55.24 | 50.16,50.87 50.16,55.24 | 50.16,50.8 57.16,50.8 | IC1.34 53.34,44.16 53.34,47.62 50.16,50.8
  Top 0.61: J5.3 J5.4 67.94,8.26 79.38,8.26 | 2.54,27.94 2.54,12.7 J1.P$37 J1.P$38 | 2.54,27.94 2.54,43.18 J1.P$13 J1.P$14 9.53,44.45 v18.41,44.45 | 2.54,27.94 J1.P$25 J1.P$26 | 97.79,27.94 97.79,43.18 | 97.79,43.18 97.79,58.42 J1.P$42 J1.P$41 | 97.79,43.18 J1.P$54 J1.P$53 | 97.79,27.94 J1.P$66 J1.P$65 | v36.83,62.23 36.83,67.31 40.01,70.48 J3.40 | 97.79,12.7 97.79,27.94 | 79.38,8.26 v79.38,8.89 | J1.P$77 J1.P$78 97.79,12.7 | 79.38,8.26 96.52,8.26 97.79,9.53 97.79,12.7
  Bottom 0.254: C1.2 C3.2 50.24,47.7 C4.2 C6.2 52.7,49.04 52.7,50.16 C8.2 | C8.2 C9.2 C7.2 C2.2 | C8.2 | R1.2 38.1,74.93 J3.40 | C118.2 74.03,9.16 74.38,8.8 J104.4 79.29,8.8 v79.38,8.89 | J1.P$38 16.88,12.7 R6.2
  Bottom 0.305: J1.P$65 86.04,23.81 | 86.04,23.81 R118.2 | 86.04,23.81 R115.2 | J2.4 17.78,71.75 19.05,73.03 J3.40
  Bottom 0.61: 52.7,70.48 40.01,70.48 J3.40 | 55.24,70.48 52.7,70.48 | 57.78,70.48 55.24,70.48 | 60.33,70.48 57.78,70.48 | 73.03,70.48 60.33,70.48 | 75.56,70.48 73.03,70.48 | 78.11,70.48 75.56,70.48 | 78.11,70.48 J3.10 | 75.56,70.48 J3.12 | 73.03,70.48 J3.14 | 60.33,70.48 J3.24 | 57.78,70.48 J3.26 | 55.24,70.48 J3.28 | 52.7,70.48 J3.30 | 22.55,55.88 IC2.2 | C15.2 22.55,55.88 | 22.55,55.88 IC2.4 | 48.26,51.44 v50.16,51.44 | 78.11,70.48 90.17,70.48 92.08,68.58 J1.P$41
  Bottom 1.016: 48.26,51.44 45.09,54.61 34.92,54.61
  other vias: 50.16,48.9 51.44,50.16 48.9,50.16
  pour Top (isolate 0.305, rank 2): 40.64,50.8 40.64,49.53 49.53,40.64 50.8,40.64 59.69,49.53 59.69,50.8 50.8,59.69 49.53,59.69
  pour Bottom (isolate 0.305, no thermals): 45.4,51.75 49.21,55.56 54.61,50.16 50.16,45.72 47.62,48.26 48.26,48.9
  pour Bottom (isolate 0.406, no thermals): 17.14,62.87 17.14,43.18 37.47,43.18 37.47,62.87

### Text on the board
Top: PDI | GND | 12V | VCC | GND | VCC | VCC | GND | GND | VCC | Dominic Rathje | VCC | GND | Christian Degenhart | GND | Oktober 2010 | Student-Lab / Uni Ulm | ATXMega Prototyping Board | v1.1 | VCC | VCC | GND | GND | VCC | PQ0 | PQ1 | PQ2 | PQ3 | PR1 | PR0 | USARTD0
bStop: PORT K | PORT J | PORT H | PORT A | PORT F | PORT B | PORT E | PORT C | PORT D
Measures: alle Maße in mm | (100,80) | (0,80) | (0,0) | (100,0)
